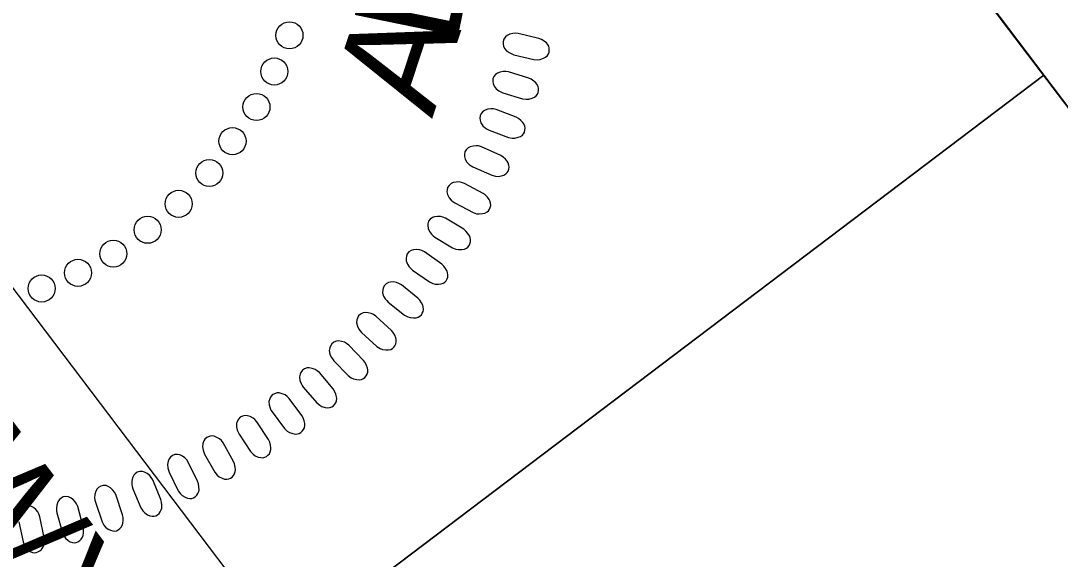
# Model space of a CAD drawing. Extents: x 475599 to 477488, y 499839 to 501843.
# Drawn here: x 475746.4 to 475807.9, y 501163.8 to 501195.7 of the extents above; entities that cross this region are included whole.
import ezdxf

# ---------------------------------------------------------------- set-up
doc = ezdxf.new("R2010")
doc.units = 0
for name, color, linetype in [('Sheet PE Seal Cell', 7, 'Continuous'), ('Sheet Plan CELL', 7, 'Continuous'), ('Sheet Sticker Exception Certification CELL', 7, 'Continuous'), ('Sheet Sticker Incomplete CELL', 7, 'Continuous')]:
    doc.layers.add(name, color=color, linetype=linetype)

msp = doc.modelspace()

# ---------------------------------------------------------------- linework, layer by layer
at = {"layer": 'Sheet PE Seal Cell'}
for points in [[(475775.589, 501193.692), (475776.783, 501193.41), (475777.005, 501193.396), (475777.153, 501193.414), (475777.344, 501193.484), (475777.473, 501193.554), (475777.576, 501193.645), (475777.639, 501193.737), (475777.684, 501193.842), (475777.69, 501193.955), (475777.689, 501194.079), (475777.655, 501194.194), (475777.582, 501194.319), (475777.518, 501194.396), (475777.388, 501194.496), (475777.227, 501194.595), (475777.077, 501194.654), (475775.855, 501194.95), (475775.686, 501194.967), (475775.539, 501194.955), (475775.364, 501194.905), (475775.201, 501194.828), (475775.102, 501194.752), (475775.007, 501194.613), (475774.954, 501194.472), (475774.958, 501194.317), (475774.983, 501194.204), (475775.05, 501194.057), (475775.187, 501193.902), (475775.347, 501193.795), (475775.466, 501193.736)], [(475774.936, 501191.437), (475776.11, 501191.081), (475776.331, 501191.053), (475776.48, 501191.061), (475776.674, 501191.12), (475776.808, 501191.181), (475776.916, 501191.266), (475776.985, 501191.354), (475777.037, 501191.456), (475777.05, 501191.568), (475777.056, 501191.692), (475777.03, 501191.81), (475776.964, 501191.938), (475776.905, 501192.019), (475776.782, 501192.127), (475776.628, 501192.236), (475776.482, 501192.304), (475775.282, 501192.676), (475775.112, 501192.704), (475774.966, 501192.701), (475774.787, 501192.662), (475774.621, 501192.596), (475774.516, 501192.526), (475774.413, 501192.393), (475774.351, 501192.255), (475774.346, 501192.101), (475774.363, 501191.986), (475774.421, 501191.835), (475774.549, 501191.672), (475774.701, 501191.555), (475774.816, 501191.489)], [(475774.131, 501189.228), (475775.281, 501188.798), (475775.499, 501188.756), (475775.648, 501188.756), (475775.847, 501188.802), (475775.983, 501188.854), (475776.098, 501188.932), (475776.171, 501189.016), (475776.229, 501189.114), (475776.249, 501189.226), (475776.264, 501189.348), (475776.244, 501189.467), (475776.187, 501189.6), (475776.134, 501189.684), (475776.017, 501189.8), (475775.87, 501189.918), (475775.729, 501189.995), (475774.554, 501190.442), (475774.388, 501190.481), (475774.24, 501190.487), (475774.06, 501190.459), (475773.89, 501190.403), (475773.781, 501190.34), (475773.67, 501190.214), (475773.599, 501190.081), (475773.584, 501189.927), (475773.594, 501189.812), (475773.643, 501189.657), (475773.76, 501189.486), (475773.905, 501189.36), (475774.016, 501189.287)], [(475773.175, 501187.054), (475774.296, 501186.552), (475774.51, 501186.497), (475774.66, 501186.488), (475774.86, 501186.521), (475775.001, 501186.565), (475775.118, 501186.635), (475775.198, 501186.714), (475775.262, 501186.808), (475775.289, 501186.919), (475775.31, 501187.04), (475775.299, 501187.16), (475775.25, 501187.296), (475775.202, 501187.384), (475775.093, 501187.506), (475774.953, 501187.634), (475774.817, 501187.72), (475773.673, 501188.24), (475773.509, 501188.288), (475773.363, 501188.304), (475773.181, 501188.287), (475773.008, 501188.242), (475772.895, 501188.186), (475772.777, 501188.067), (475772.697, 501187.938), (475772.673, 501187.786), (475772.675, 501187.67), (475772.714, 501187.513), (475772.821, 501187.335), (475772.957, 501187.2), (475773.063, 501187.12)], [(475772.094, 501184.922), (475773.181, 501184.351), (475773.392, 501184.283), (475773.54, 501184.264), (475773.742, 501184.285), (475773.885, 501184.32), (475774.008, 501184.382), (475774.091, 501184.456), (475774.161, 501184.546), (475774.195, 501184.654), (475774.224, 501184.775), (475774.22, 501184.895), (475774.18, 501185.034), (475774.138, 501185.124), (475774.037, 501185.253), (475773.905, 501185.389), (475773.775, 501185.483), (475772.665, 501186.074), (475772.504, 501186.133), (475772.36, 501186.158), (475772.178, 501186.153), (475772.002, 501186.119), (475771.886, 501186.07), (475771.76, 501185.958), (475771.672, 501185.835), (475771.639, 501185.684), (475771.634, 501185.568), (475771.663, 501185.409), (475771.758, 501185.225), (475771.886, 501185.082), (475771.986, 501184.995)], [(475770.915, 501182.901), (475771.963, 501182.264), (475772.171, 501182.182), (475772.317, 501182.153), (475772.52, 501182.161), (475772.665, 501182.188), (475772.791, 501182.242), (475772.879, 501182.31), (475772.955, 501182.396), (475772.996, 501182.502), (475773.032, 501182.62), (475773.036, 501182.74), (475773.004, 501182.881), (475772.968, 501182.974), (475772.874, 501183.11), (475772.752, 501183.253), (475772.628, 501183.356), (475771.558, 501184.015), (475771.401, 501184.084), (475771.259, 501184.118), (475771.076, 501184.124), (475770.898, 501184.101), (475770.779, 501184.059), (475770.647, 501183.956), (475770.552, 501183.839), (475770.509, 501183.691), (475770.497, 501183.575), (475770.516, 501183.415), (475770.599, 501183.225), (475770.717, 501183.074), (475770.813, 501182.981)], [(475769.59, 501180.946), (475770.596, 501180.244), (475770.797, 501180.149), (475770.941, 501180.112), (475771.145, 501180.107), (475771.291, 501180.124), (475771.42, 501180.171), (475771.512, 501180.233), (475771.593, 501180.314), (475771.64, 501180.417), (475771.684, 501180.533), (475771.695, 501180.652), (475771.673, 501180.795), (475771.643, 501180.89), (475771.558, 501181.031), (475771.445, 501181.183), (475771.327, 501181.292), (475770.3, 501182.017), (475770.148, 501182.096), (475770.008, 501182.139), (475769.827, 501182.156), (475769.648, 501182.145), (475769.527, 501182.111), (475769.388, 501182.016), (475769.286, 501181.904), (475769.233, 501181.759), (475769.214, 501181.645), (475769.223, 501181.484), (475769.294, 501181.289), (475769.402, 501181.131), (475769.492, 501181.032)], [(475768.163, 501179.046), (475769.123, 501178.282), (475769.318, 501178.176), (475769.46, 501178.129), (475769.663, 501178.111), (475769.809, 501178.119), (475769.941, 501178.157), (475770.037, 501178.215), (475770.123, 501178.29), (475770.177, 501178.39), (475770.228, 501178.502), (475770.247, 501178.621), (475770.233, 501178.765), (475770.208, 501178.862), (475770.133, 501179.007), (475770.03, 501179.166), (475769.919, 501179.283), (475768.94, 501180.071), (475768.793, 501180.159), (475768.656, 501180.21), (475768.475, 501180.24), (475768.296, 501180.239), (475768.174, 501180.213), (475768.029, 501180.127), (475767.92, 501180.022), (475767.859, 501179.881), (475767.833, 501179.767), (475767.831, 501179.606), (475767.89, 501179.407), (475767.988, 501179.242), (475768.071, 501179.139)], [(475766.586, 501177.251), (475767.496, 501176.428), (475767.684, 501176.309), (475767.822, 501176.254), (475768.024, 501176.224), (475768.17, 501176.222), (475768.305, 501176.252), (475768.404, 501176.303), (475768.494, 501176.373), (475768.554, 501176.469), (475768.612, 501176.578), (475768.639, 501176.696), (475768.634, 501176.84), (475768.615, 501176.938), (475768.55, 501177.089), (475768.456, 501177.253), (475768.353, 501177.377), (475767.426, 501178.225), (475767.285, 501178.321), (475767.151, 501178.382), (475766.973, 501178.422), (475766.794, 501178.433), (475766.669, 501178.414), (475766.52, 501178.338), (475766.405, 501178.24), (475766.334, 501178.103), (475766.301, 501177.991), (475766.29, 501177.831), (475766.336, 501177.628), (475766.424, 501177.457), (475766.5, 501177.349)], [(475764.933, 501175.582), (475765.79, 501174.703), (475765.97, 501174.573), (475766.105, 501174.509), (475766.304, 501174.466), (475766.45, 501174.455), (475766.586, 501174.477), (475766.688, 501174.522), (475766.783, 501174.586), (475766.849, 501174.678), (475766.913, 501174.783), (475766.947, 501174.899), (475766.952, 501175.044), (475766.939, 501175.143), (475766.883, 501175.296), (475766.8, 501175.467), (475766.705, 501175.596), (475765.832, 501176.501), (475765.698, 501176.607), (475765.568, 501176.675), (475765.393, 501176.727), (475765.215, 501176.749), (475765.09, 501176.738), (475764.935, 501176.671), (475764.815, 501176.58), (475764.735, 501176.448), (475764.695, 501176.339), (475764.674, 501176.179), (475764.707, 501175.974), (475764.784, 501175.799), (475764.853, 501175.685)], [(475763.134, 501174.013), (475763.934, 501173.083), (475764.105, 501172.941), (475764.236, 501172.869), (475764.432, 501172.814), (475764.577, 501172.794), (475764.714, 501172.807), (475764.819, 501172.845), (475764.917, 501172.903), (475764.989, 501172.991), (475765.06, 501173.092), (475765.101, 501173.205), (475765.115, 501173.349), (475765.108, 501173.449), (475765.062, 501173.606), (475764.99, 501173.781), (475764.903, 501173.916), (475764.089, 501174.874), (475763.961, 501174.988), (475763.836, 501175.064), (475763.664, 501175.127), (475763.488, 501175.16), (475763.363, 501175.157), (475763.204, 501175.1), (475763.078, 501175.017), (475762.991, 501174.89), (475762.944, 501174.783), (475762.913, 501174.625), (475762.933, 501174.419), (475762.999, 501174.239), (475763.061, 501174.121)], [(475761.286, 501172.549), (475762.026, 501171.57), (475762.188, 501171.418), (475762.314, 501171.337), (475762.506, 501171.27), (475762.65, 501171.241), (475762.787, 501171.246), (475762.894, 501171.277), (475762.996, 501171.329), (475763.073, 501171.412), (475763.15, 501171.508), (475763.198, 501171.618), (475763.221, 501171.762), (475763.221, 501171.861), (475763.184, 501172.021), (475763.123, 501172.2), (475763.045, 501172.341), (475762.293, 501173.348), (475762.173, 501173.47), (475762.053, 501173.554), (475761.885, 501173.627), (475761.711, 501173.671), (475761.586, 501173.676), (475761.424, 501173.629), (475761.293, 501173.554), (475761.198, 501173.432), (475761.145, 501173.329), (475761.103, 501173.173), (475761.11, 501172.966), (475761.165, 501172.782), (475761.219, 501172.661)], [(475759.333, 501171.233), (475760.01, 501170.211), (475760.162, 501170.048), (475760.283, 501169.96), (475760.47, 501169.881), (475760.612, 501169.843), (475760.749, 501169.838), (475760.858, 501169.863), (475760.963, 501169.908), (475761.045, 501169.987), (475761.129, 501170.078), (475761.183, 501170.185), (475761.215, 501170.326), (475761.221, 501170.426), (475761.195, 501170.588), (475761.145, 501170.77), (475761.076, 501170.916), (475760.388, 501171.968), (475760.276, 501172.097), (475760.162, 501172.188), (475759.998, 501172.272), (475759.828, 501172.327), (475759.703, 501172.34), (475759.539, 501172.303), (475759.403, 501172.237), (475759.301, 501172.121), (475759.241, 501172.021), (475759.19, 501171.868), (475759.184, 501171.661), (475759.227, 501171.474), (475759.274, 501171.35)], [(475757.291, 501170.047), (475757.903, 501168.984), (475758.044, 501168.812), (475758.159, 501168.717), (475758.341, 501168.626), (475758.48, 501168.579), (475758.617, 501168.566), (475758.727, 501168.584), (475758.835, 501168.622), (475758.922, 501168.695), (475759.011, 501168.781), (475759.072, 501168.885), (475759.112, 501169.024), (475759.124, 501169.123), (475759.108, 501169.286), (475759.071, 501169.471), (475759.011, 501169.621), (475758.391, 501170.714), (475758.286, 501170.85), (475758.178, 501170.948), (475758.021, 501171.042), (475757.854, 501171.107), (475757.73, 501171.127), (475757.564, 501171.101), (475757.424, 501171.044), (475757.315, 501170.935), (475757.249, 501170.839), (475757.188, 501170.69), (475757.17, 501170.483), (475757.201, 501170.294), (475757.239, 501170.167)], [(475755.192, 501168.986), (475755.736, 501167.886), (475755.866, 501167.706), (475755.975, 501167.603), (475756.151, 501167.501), (475756.286, 501167.446), (475756.423, 501167.424), (475756.534, 501167.435), (475756.643, 501167.466), (475756.734, 501167.534), (475756.829, 501167.614), (475756.896, 501167.713), (475756.945, 501167.85), (475756.964, 501167.948), (475756.958, 501168.112), (475756.932, 501168.299), (475756.882, 501168.452), (475756.331, 501169.583), (475756.236, 501169.724), (475756.133, 501169.829), (475755.983, 501169.932), (475755.821, 501170.008), (475755.698, 501170.036), (475755.531, 501170.021), (475755.388, 501169.972), (475755.271, 501169.87), (475755.2, 501169.779), (475755.13, 501169.633), (475755.098, 501169.429), (475755.117, 501169.237), (475755.148, 501169.108)], [(475753.053, 501168.008), (475753.527, 501166.876), (475753.646, 501166.688), (475753.748, 501166.579), (475753.917, 501166.466), (475754.049, 501166.402), (475754.183, 501166.371), (475754.295, 501166.376), (475754.406, 501166.4), (475754.502, 501166.462), (475754.601, 501166.536), (475754.674, 501166.631), (475754.732, 501166.764), (475754.757, 501166.86), (475754.761, 501167.025), (475754.746, 501167.213), (475754.706, 501167.369), (475754.228, 501168.531), (475754.141, 501168.679), (475754.046, 501168.79), (475753.902, 501168.903), (475753.745, 501168.988), (475753.624, 501169.025), (475753.456, 501169.019), (475753.311, 501168.98), (475753.188, 501168.885), (475753.111, 501168.799), (475753.032, 501168.658), (475752.987, 501168.456), (475752.994, 501168.264), (475753.017, 501168.133)], [(475750.829, 501167.208), (475751.231, 501166.049), (475751.338, 501165.854), (475751.433, 501165.738), (475751.595, 501165.615), (475751.723, 501165.543), (475751.855, 501165.505), (475751.966, 501165.501), (475752.079, 501165.52), (475752.178, 501165.575), (475752.282, 501165.642), (475752.36, 501165.733), (475752.427, 501165.861), (475752.457, 501165.957), (475752.472, 501166.12), (475752.47, 501166.309), (475752.439, 501166.467), (475752.035, 501167.657), (475751.958, 501167.81), (475751.869, 501167.927), (475751.733, 501168.048), (475751.581, 501168.143), (475751.463, 501168.188), (475751.295, 501168.193), (475751.148, 501168.162), (475751.019, 501168.075), (475750.937, 501167.994), (475750.849, 501167.859), (475750.792, 501167.659), (475750.787, 501167.467), (475750.801, 501167.335)], [(475748.555, 501166.585), (475748.883, 501165.403), (475748.978, 501165.202), (475749.065, 501165.081), (475749.219, 501164.947), (475749.342, 501164.868), (475749.471, 501164.821), (475749.583, 501164.811), (475749.697, 501164.821), (475749.799, 501164.871), (475749.906, 501164.932), (475749.991, 501165.016), (475750.065, 501165.141), (475750.102, 501165.234), (475750.126, 501165.396), (475750.135, 501165.585), (475750.115, 501165.745), (475749.786, 501166.957), (475749.719, 501167.114), (475749.638, 501167.237), (475749.51, 501167.367), (475749.364, 501167.472), (475749.249, 501167.523), (475749.082, 501167.539), (475748.933, 501167.518), (475748.8, 501167.439), (475748.712, 501167.363), (475748.616, 501167.233), (475748.546, 501167.038), (475748.53, 501166.846), (475748.535, 501166.713)]]:
    msp.add_lwpolyline(points, close=True, dxfattribs=at)
msp.add_lwpolyline([(475746.299, 501166.055), (475746.552, 501164.855), (475746.634, 501164.648), (475746.714, 501164.522), (475746.858, 501164.379), (475746.976, 501164.292), (475747.102, 501164.237), (475747.213, 501164.219), (475747.327, 501164.223), (475747.432, 501164.266), (475747.543, 501164.32), (475747.633, 501164.399), (475747.715, 501164.519), (475747.757, 501164.609), (475747.792, 501164.77), (475747.814, 501164.958), (475747.803, 501165.118), (475747.551, 501166.35), (475747.494, 501166.511), (475747.421, 501166.638), (475747.3, 501166.776), (475747.162, 501166.889), (475747.051, 501166.947), (475746.884, 501166.974), (475746.734, 501166.962), (475746.596, 501166.892), (475746.504, 501166.822), (475746.4, 501166.698)], dxfattribs=at)
for centre in [(475762.315, 501194.837), (475761.423, 501192.696), (475760.363, 501190.597), (475758.945, 501188.575), (475757.574, 501186.69), (475755.757, 501184.866), (475753.923, 501183.329), (475751.892, 501181.912), (475749.801, 501180.78), (475747.654, 501179.855)]:
    msp.add_circle(centre, 0.801, dxfattribs=at)
at = {"layer": 'Sheet Plan CELL'}
msp.add_line((475717.254, 501124.582), (475806.917, 501192.468), dxfattribs=at)
for points in [[(477369.494, 500619.368), (476532.299, 499985.628), (475747.678, 501022.142), (475867.321, 501112.709), (475746.601, 501272.214), (476464.153, 501815.359)], [(475717.254, 501124.582), (475656.898, 501204.298), (475746.601, 501272.214), (475806.965, 501192.488)], [(475777.638, 501044.809), (475717.254, 501124.582), (475806.965, 501192.488), (475867.321, 501112.709)]]:
    msp.add_lwpolyline(points, close=True, dxfattribs=at)
at = {"layer": 'Sheet Sticker Exception Certification CELL'}
msp.add_line((475867.321, 501112.709), (475746.591, 501272.206), dxfattribs=at)
msp.add_line((475867.321, 501112.709), (475746.591, 501272.206), dxfattribs=at)
at = {"layer": 'Sheet Sticker Incomplete CELL'}
msp.add_lwpolyline([(475806.465, 501099.927), (475787.727, 501085.744), (475699.007, 501202.952), (475717.745, 501217.135)], close=True, dxfattribs=at)

# ---------------------------------------------------------------- texts
at = {"layer": 'Sheet PE Seal Cell'}
for s, rotation, p in [('L', 78.42676, (475772.156, 501194.124)), ('A', 71.80709, (475770.755, 501189.878))]:
    msp.add_text(s, height=6.236, rotation=rotation, dxfattribs=at).set_placement(p)
at = {"layer": 'Sheet Sticker Exception Certification CELL'}
for s, p in [('UNLESS ALL SIGNATURES COMPLETED', (475872.93, 501137.021)), ('UNLESS ALL SIGNATURES COMPLETED', (475872.93, 501137.021)), ('DOCUMENT NOT CONSIDERED FINAL', (475862.853, 501135.754)), ('DOCUMENT NOT CONSIDERED FINAL', (475862.853, 501135.754))]:
    msp.add_text(s, height=5.5, rotation=127.12364, dxfattribs=at).set_placement(p)
at = {"layer": 'Sheet Sticker Incomplete CELL'}
for s, height, p in [('INCOMPLETE PLANS', 11.52, (475791.734, 501100.002)), ('DO NOT USE FOR R/W ACQUISITION', 5.76, (475795.314, 501106.788))]:
    msp.add_text(s, height=height, rotation=127.12364, dxfattribs=at).set_placement(p)

doc.saveas('drawing.dxf')
